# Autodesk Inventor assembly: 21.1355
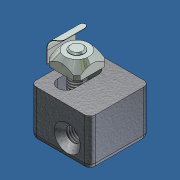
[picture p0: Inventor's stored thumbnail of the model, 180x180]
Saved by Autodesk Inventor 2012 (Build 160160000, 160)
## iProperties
Created: 2007-04
Part Number: 21.1355
Document SubType Name: Assembly
Designer: Andy Moles
Mass: 35.878 g
Surface Area: 55.2893 cm^2
Volume: 10.2565 cm^3
Density: 3.49809 g/cm^3
Description: MULTIBLOCK GD
Author: Andy Moles
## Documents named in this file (4)
- C:\Andys Backup Data\ANDY'S INVENTOR\INVENTOR LIBRARIES\PARTS LIBRARY\FITTING OF PANEL ELEMENTS ASSEMBLY POSSIBILITIES\21.1355 MULTIBLOCK GD.iam
- C:\Andys Backup Data\ANDY'S INVENTOR\INVENTOR LIBRARIES\PARTS LIBRARY\FITTING OF PANEL ELEMENTS ASSEMBLY POSSIBILITIES\SUBCOMPONENTS\21.1355 MULTIBLOCK GD.ipt
- C:\Andys Backup Data\ANDY'S INVENTOR\INVENTOR LIBRARIES\PARTS LIBRARY\FASTENING ELEMENTS\SCREWS CAP\21.1242 M6X25.ipt
- C:\Andys Backup Data\ANDY'S INVENTOR\INVENTOR LIBRARIES\PARTS LIBRARY\FASTENING ELEMENTS\NUTS\21.1330_2 M6 SQUARE NUT POS FXG.ipt
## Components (3 placed, 3 different names)
1. 21.1355 MULTIBLOCK GD:1 — Flush:1, Mate:1, Flush:2, Mate:2, Tangent:1, Tangent:2, Mate:4, Angle:1
2. 21.1242 M6 x 25 SHCS:1 — Mate:2, Tangent:1, Tangent:2, Mate:3
3. 21.1330_2 M6 SQUARE NUT POS FXG:1 — Mate:3, Mate:4, Angle:1
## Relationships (9: Mate 4, Flush 2, Tangent 2, Angle 1)
- Flush:1: 21.1355 MULTIBLOCK GD:1
- Mate:1: 21.1355 MULTIBLOCK GD:1
- Flush:2: 21.1355 MULTIBLOCK GD:1
- Mate:2: 21.1355 MULTIBLOCK GD:1 ↔ 21.1242 M6 x 25 SHCS:1
- Tangent:1: 21.1355 MULTIBLOCK GD:1 ↔ 21.1242 M6 x 25 SHCS:1
- Tangent:2: 21.1355 MULTIBLOCK GD:1 ↔ 21.1242 M6 x 25 SHCS:1
- Mate:3: 21.1242 M6 x 25 SHCS:1 ↔ 21.1330_2 M6 SQUARE NUT POS FXG:1
- Mate:4: 21.1355 MULTIBLOCK GD:1 ↔ 21.1330_2 M6 SQUARE NUT POS FXG:1
- Angle:1: 21.1355 MULTIBLOCK GD:1 ↔ 21.1330_2 M6 SQUARE NUT POS FXG:1
